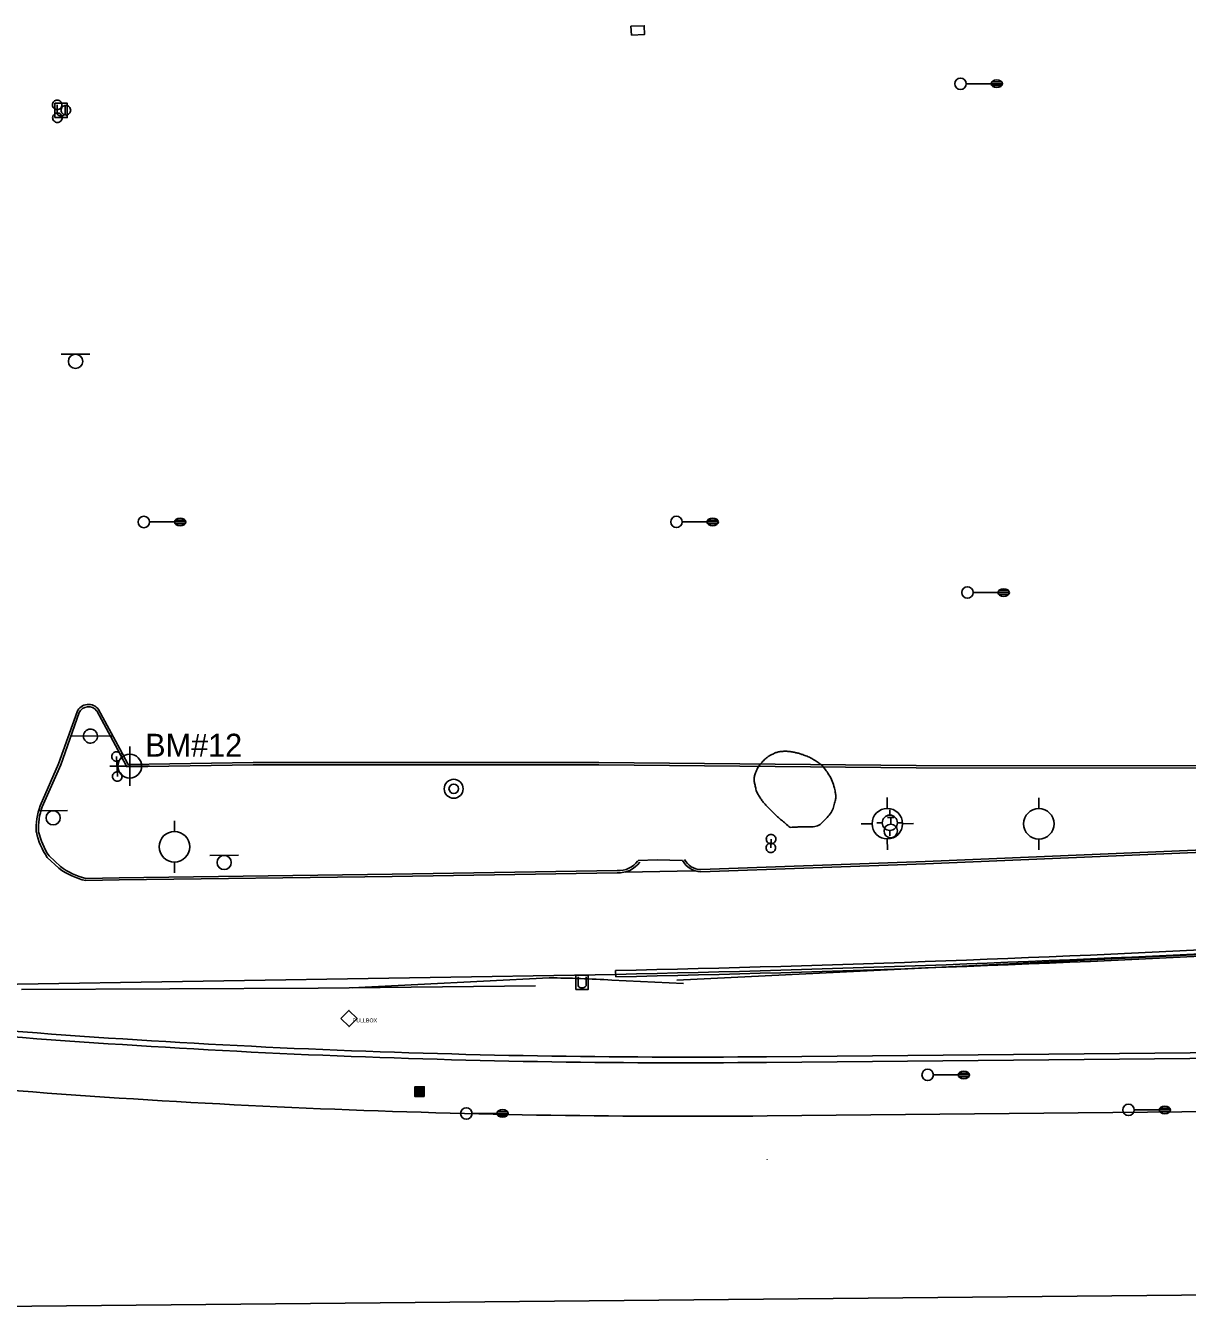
# Model space of a CAD drawing. Extents: x 2145380 to 2157287, y 139568 to 149130.
# Drawn here: x 2146552.5 to 2146856.9, y 143062 to 143399.4 of the extents above; entities that cross this region are included whole.
import ezdxf

# ---------------------------------------------------------------- set-up
doc = ezdxf.new("R2010")
doc.units = 0
for name, color, linetype in [('Default', 7, 'Continuous'), ('PR_PREVIOUSLY CONSTRUCTED', 7, 'Continuous'), ('SURV_Benchmark', 7, 'Continuous'), ('TOPO_Asphalt', 7, 'Continuous'), ('TOPO_Concrete', 7, 'Continuous'), ('TOPO_Curb Back', 7, 'Continuous'), ('TOPO_DRAIN_Inlet Grate', 7, 'Continuous'), ('TOPO_Guardrail', 7, 'Continuous'), ('TOPO_Light Pole', 7, 'Continuous'), ('TOPO_Misc', 7, 'Continuous'), ('TOPO_Power Pole', 7, 'Continuous'), ('TOPO_Power Pullbox', 7, 'Continuous'), ('TOPO_San Manhole', 7, 'Continuous'), ('TOPO_Sign', 7, 'Continuous'), ('TOPO_Tree Line', 7, 'Continuous'), ('TOPO_Water Fire Hydrant', 7, 'Continuous'), ('TOPO_Water Valve', 7, 'Continuous')]:
    doc.layers.add(name, color=color, linetype=linetype)

# ---------------------------------------------------------------- blocks, each defined once
blk = doc.blocks.new('LP')
at = {"layer": 'TOPO_Light Pole'}
blk.add_line((3.81, 0), (20.32, 0), dxfattribs=at)
for points in [[(20.32, 0), (27.94, 0)], [(20.32, 0), (23.5, 0)], [(20.83, 1.27), (27.43, 1.27)], [(20.83, 1.27), (23.5, 1.27)], [(23.71, 1.27), (27.43, 1.27)], [(23.71, 0), (27.94, 0)], [(20.83, -1.27), (27.43, -1.27)], [(20.83, -1.27), (23.5, -1.27)], [(23.71, -1.27), (27.43, -1.27)]]:
    blk.add_lwpolyline(points, dxfattribs=at)
blk.add_circle((0, 0), 3.81, dxfattribs=at)
blk.add_ellipse((24.13, 0), major_axis=(3.81, 0), ratio=0.666667, dxfattribs=at)
blk = doc.blocks.new('POST')
at = {"layer": 'TOPO_Misc'}
for start, end in [(89.99996, 180.00004), (179.99996, 270.00004), (359.99996, 90.00004), (269.99996, 0.00004)]:
    blk.add_arc((-0.01, 0.03), 3.16, start, end, dxfattribs=at)
blk = doc.blocks.new('FIRHYD')
at = {"layer": 'TOPO_Water Fire Hydrant'}
for p, q in [((-0.02, 10.16), (-0.03, 17.34)), ((10.16, 0.02), (17.34, 0.03)), ((-10.16, -0.02), (-17.34, -0.03)), ((0.02, -10.16), (0.03, -17.34))]:
    blk.add_line(p, q, dxfattribs=at)
blk.add_circle((0, 0), 10.16, dxfattribs=at)
blk = doc.blocks.new('CB')
at = {"layer": 'TOPO_Misc'}
for p, q in [((-3.08, 2.99), (3.24, 2.99)), ((-3.08, 2.68), (3.24, 2.68)), ((-3.08, 2.36), (3.24, 2.36)), ((-3.08, 2.05), (3.24, 2.05)), ((-3.08, 1.73), (3.24, 1.73)), ((-3.08, 1.4), (3.24, 1.4)), ((-3.08, 1.1), (3.24, 1.1)), ((-3.08, 0.77), (3.24, 0.77)), ((-3.08, 0.46), (3.24, 0.46)), ((-3.08, 0.14), (3.24, 0.14)), ((-3.08, -0.17), (3.24, -0.17)), ((-3.08, -0.48), (3.24, -0.48)), ((-3.08, -0.8), (3.24, -0.8)), ((-3.08, -1.11), (3.26, -1.11)), ((-3.08, -1.43), (3.26, -1.43)), ((-3.08, -1.75), (3.26, -1.75)), ((-3.08, -2.07), (3.26, -2.07)), ((-3.08, -2.39), (3.26, -2.39)), ((-3.08, -2.7), (3.26, -2.7)), ((-3.08, -3.02), (3.26, -3.02))]:
    blk.add_line(p, q, dxfattribs=at)
blk.add_lwpolyline([(3.26, -3.29), (3.24, 3.05), (-3.09, 3.04), (-3.08, -3.3), (3.26, -3.29)], dxfattribs=at)
blk = doc.blocks.new('POWPOL')
at = {"layer": 'TOPO_Power Pole'}
for p, q in [((0, 10.16), (0, 17.34)), ((0, -10.16), (0, -17.34))]:
    blk.add_line(p, q, dxfattribs=at)
blk.add_circle((0, 0), 10.16, dxfattribs=at)
blk = doc.blocks.new('pulbox')
at = {"layer": 'Default'}
blk.add_lwpolyline([(-5.38, -0.01), (-0.02, 5.42), (5.4, 0.06), (0.05, -5.36), (-5.38, -0.01)], dxfattribs=at)
blk.add_text('PULLBOX', height=2.54, dxfattribs=at).set_placement((2.54, -2.54))
blk = doc.blocks.new('WATVAL')
at = {"layer": 'Default'}
for p, q in [((-2.25, 9), (2.25, 9)), ((0, 4.5), (0, 9))]:
    blk.add_line(p, q, dxfattribs=at)
blk.add_circle((0, 0), 4.5, dxfattribs=at)
blk = doc.blocks.new('EXMHSS')
at = {"layer": 'Default'}
for radius in [6.3, 3.13]:
    blk.add_circle((0, 0), radius, dxfattribs=at)
blk = doc.blocks.new('BM')
at = {"layer": 'SURV_Benchmark'}
for p, q in [((0, 2.49), (0, 4.15)), ((-2.49, 0), (-4.16, 0)), ((4.16, 0), (2.49, 0)), ((0, -4.16), (0, -2.49))]:
    blk.add_line(p, q, dxfattribs=at)
for points in [[(-2.5, 0), (-2.49, 0), (0, 0), (0, -2.49), (0, -2.49)], [(-2.5, 0), (-2.49, 0), (0, 0), (0, -2.49), (0, -2.49)], [(0, 2.49), (0, 2.49), (0, 0), (2.49, 0), (2.49, 0), (2.49, 0)], [(0, 2.49), (0, 2.49), (0, 0), (2.49, 0), (2.49, 0), (2.49, 0), (2.49, 0)]]:
    blk.add_lwpolyline(points, dxfattribs=at)
for start, end in [(90.0638, 180.0068), (0.0638, 90.0068), (0.0638, 90.0068), (180.0638, 270.0068), (180.0638, 270.0068), (269.9472, 359.9927)]:
    blk.add_arc((0, 0), 2.5, start, end, dxfattribs=at)

msp = doc.modelspace()

# ---------------------------------------------------------------- linework, layer by layer
at = {"layer": 'PR_PREVIOUSLY CONSTRUCTED'}
for p, q in [((2146707.09, 143150.12), (2146707.05, 143151.78)), ((2146746.76, 143113.71), (2147732.05, 143123.05)), ((2146353.97, 143061.98), (2147732.51, 143075.05))]:
    msp.add_line(p, q, dxfattribs=at)
for points in [[(2146746.61, 143129.21), (2147125.89, 143132.8), (2147166.18, 143125.18), (2147422.32, 143127.61), (2147722.25, 143136.46), (2147731.92, 143136.55)], [(2146746.63, 143127.71), (2147125.75, 143131.3), (2147166.04, 143123.68), (2147422.35, 143126.11), (2147722.28, 143134.96), (2147731.94, 143135.05)]]:
    msp.add_lwpolyline(points, dxfattribs=at)
for centre, radius, start, end in [((2146580.58, 148904.97), 5754.58, 271.259323, 272.983717), ((2146580.58, 148904.97), 5755.58, 271.259323, 272.983717), ((2146580.58, 148904.97), 5756.24, 271.259323, 272.983717), ((2146725.03, 145405.44), 2277.83, 264.5, 270.54316), ((2146725.03, 145405.44), 2276.33, 264.5, 270.54316), ((2146725.03, 145405.43), 2291.83, 264.5, 270.54316)]:
    msp.add_arc(centre, radius, start, end, dxfattribs=at)
at = {"layer": 'TOPO_Asphalt'}
for p, q in [((2146576.46, 143202.65), (2146576.24, 143207.86)), ((2146727.7, 143177.96), (2146709.51, 143177.61)), ((2146537.09, 143147.98), (2146707.07, 143150.78))]:
    msp.add_line(p, q, dxfattribs=at)
msp.add_lwpolyline([(2146712.97, 143180.61), (2146717.98, 143180.83), (2146724.61, 143180.64)], dxfattribs=at)
at = {"layer": 'TOPO_Concrete'}
msp.add_lwpolyline([(2146746.75, 143102.26), (2146746.75, 143102.21)], dxfattribs=at)
at = {"layer": 'TOPO_Curb Back'}
for points in [[(2146556.23, 143194.94), (2146561.06, 143205.93), (2146565.9, 143219.62)], [(2146556.79, 143194.71), (2146561.62, 143205.7), (2146566.46, 143219.39)], [(2146571.05, 143219.87), (2146576.58, 143209.64), (2146578.98, 143205.21), (2146612.05, 143205.72), (2146702.61, 143205.68), (2146785.83, 143204.89), (2146866.96, 143204.87), (2146925.47, 143204.4), (2146939.15, 143204.34), (2146943.78, 143207.95), (2146941.54, 143212.17)], [(2146571.55, 143220.19), (2146577.11, 143209.93), (2146579.34, 143205.82), (2146612.05, 143206.32), (2146702.61, 143206.28), (2146785.83, 143205.49), (2146866.96, 143205.47), (2146925.48, 143205), (2146938.94, 143204.94), (2146943.01, 143208.11), (2146941.09, 143211.74)], [(2146936.56, 143186.42), (2146861.15, 143182.86), (2146788.22, 143179.79), (2146729.35, 143177.64)], [(2146936.54, 143187.02), (2146861.12, 143183.46), (2146788.2, 143180.39), (2146729.36, 143178.24)], [(2146561.15, 143178.6), (2146558.1, 143181.44)], [(2146561.53, 143179.06), (2146558.56, 143181.83)], [(2146707.46, 143177.43), (2146648.5, 143176.48), (2146576.92, 143175.53), (2146568.17, 143175.36)], [(2146707.48, 143178.03), (2146648.49, 143177.08), (2146576.91, 143176.13), (2146568.24, 143175.96)], [(2146723.1, 143149.31), (2147096.93, 143167.63)]]:
    msp.add_lwpolyline(points, dxfattribs=at)
for centre, radius, start, end in [((2146568.89, 143218.27), 3.28, 35.8736, 155.7101), ((2146568.89, 143218.27), 2.68, 36.6665, 155.1999), ((2146571.29, 143189.22), 16.1, 159.2169, 184.0265), ((2146571.29, 143189.22), 15.5, 159.2728, 183.8644), ((2146573.83, 143192.18), 18.44, 192.5386, 214.1261), ((2146573.83, 143192.18), 19.04, 192.4019, 214.3313), ((2146572.65, 143194.28), 19.45, 233.753, 256.6902), ((2146572.65, 143194.28), 18.85, 233.8598, 256.4606), ((2146707.92, 143184.13), 6.71, 266.1076, 324.0825), ((2146707.92, 143184.13), 6.11, 265.8766, 324.0825), ((2146729.6, 143183.28), 5.65, 207.8693, 267.5079), ((2146729.6, 143183.28), 5.05, 207.8693, 267.2427)]:
    msp.add_arc(centre, radius, start, end, dxfattribs=at)
at = {"layer": 'TOPO_DRAIN_Inlet Grate'}
msp.add_lwpolyline([(2146711.19, 143396.97), (2146714.64, 143397.13), (2146714.54, 143399.4), (2146711.08, 143399.25)], close=True, dxfattribs=at)
at = {"layer": 'TOPO_Guardrail'}
for points in [[(2146551.37, 143146.86), (2146629.12, 143147.21), (2146686.04, 143147.75)], [(2146637.99, 143147.3), (2146689.63, 143149.87)], [(2146706.03, 143149.31), (2146724.88, 143148.43)]]:
    msp.add_lwpolyline(points, dxfattribs=at)
msp.add_arc((2146685.9, 142804.41), 345.49, 86.6594, 89.3802, dxfattribs=at)
at = {"layer": 'TOPO_Misc'}
for p, q in [((2146560.67, 143378.66), (2146560.67, 143376.26)), ((2146562.75, 143376.26), (2146562.75, 143378.67)), ((2146697.21, 143150.16), (2146697.21, 143147.76)), ((2146699.29, 143147.76), (2146699.29, 143150.17))]:
    msp.add_line(p, q, dxfattribs=at)
for points in [[(2146560.08, 143375.35), (2146560.08, 143379.11), (2146563.34, 143379.11), (2146563.34, 143375.35), (2146560.08, 143375.35)], [(2146696.62, 143146.85), (2146696.62, 143150.61), (2146699.88, 143150.61), (2146699.88, 143146.85), (2146696.62, 143146.85)]]:
    msp.add_lwpolyline(points, dxfattribs=at)
for centre in [(2146561.71, 143377.08), (2146698.25, 143148.58)]:
    msp.add_arc(centre, 1.32, 218.3412, 322.0625, dxfattribs=at)
at = {"layer": 'TOPO_Sign'}
for points in [[(2146561.76, 143313.31), (2146569.26, 143313.32)], [(2146565.51, 143313.31), (2146565.51, 143313.31)], [(2146563.65, 143311.45), (2146563.65, 143311.45)], [(2146567.38, 143311.45), (2146567.38, 143311.45)], [(2146565.51, 143309.58), (2146565.51, 143309.58)], [(2146564.27, 143213.21), (2146575.15, 143213.27)], [(2146555.89, 143193.69), (2146563.38, 143193.7)], [(2146557.77, 143191.82), (2146557.77, 143191.82)], [(2146559.64, 143193.69), (2146559.64, 143193.69)], [(2146561.51, 143191.82), (2146561.51, 143191.82)], [(2146559.64, 143189.95), (2146559.64, 143189.95)], [(2146747.71, 143183.96), (2146747.78, 143186.22)], [(2146600.71, 143181.98), (2146608.2, 143181.99)], [(2146604.46, 143181.98), (2146604.46, 143181.98)], [(2146602.59, 143180.11), (2146602.59, 143180.11)], [(2146604.46, 143178.24), (2146604.46, 143178.24)], [(2146606.32, 143180.11), (2146606.32, 143180.11)]]:
    msp.add_lwpolyline(points, dxfattribs=at)
for centre, radius, start, end in [((2146565.51, 143311.45), 1.87, 90, 180), ((2146565.51, 143311.45), 1.87, 360, 90), ((2146565.51, 143311.45), 1.87, 180, 270), ((2146565.51, 143311.45), 1.87, 270, 0), ((2146569.41, 143213.23), 1.84, 47.4196, 227.4196), ((2146569.41, 143213.23), 1.84, 227.4196, 47.4196), ((2146559.64, 143191.82), 1.87, 90, 180), ((2146559.64, 143191.82), 1.87, 180, 270), ((2146559.64, 143191.82), 1.87, 360, 90), ((2146559.64, 143191.82), 1.87, 270, 0), ((2146604.46, 143180.11), 1.87, 90, 180), ((2146604.46, 143180.11), 1.87, 360, 90), ((2146604.46, 143180.11), 1.87, 180, 270), ((2146604.46, 143180.11), 1.87, 270, 0)]:
    msp.add_arc(centre, radius, start, end, dxfattribs=at)
at = {"layer": 'TOPO_Tree Line'}
msp.add_open_spline([(2146752.76, 143189.3), (2146753.6, 143189.35), (2146754.44, 143189.4), (2146755.28, 143189.45), (2146756.33, 143189.51), (2146757.38, 143189.38), (2146758.43, 143189.46), (2146760, 143189.56), (2146761.28, 143190.6), (2146762.46, 143191.91), (2146763.62, 143193.2), (2146764.18, 143194.55), (2146764.54, 143196.07), (2146764.75, 143196.93), (2146764.78, 143197.84), (2146764.59, 143198.68), (2146764.18, 143200.55), (2146763.52, 143202.31), (2146762.38, 143203.98), (2146761.75, 143204.9), (2146761.06, 143205.63), (2146760.18, 143206.26), (2146759.02, 143207.08), (2146757.86, 143207.71), (2146756.56, 143208.21), (2146755.67, 143208.55), (2146754.77, 143208.79), (2146753.85, 143208.98), (2146752.77, 143209.19), (2146751.66, 143209.29), (2146750.58, 143209.21), (2146749.7, 143209.14), (2146748.86, 143208.84), (2146748.02, 143208.42), (2146747.22, 143208.03), (2146746.57, 143207.57), (2146745.93, 143206.93), (2146744.92, 143205.93), (2146744.21, 143204.87), (2146743.73, 143203.57), (2146743.37, 143202.63), (2146743.34, 143201.59), (2146743.53, 143200.65), (2146743.75, 143199.56), (2146744.06, 143198.47), (2146744.68, 143197.47), (2146745.25, 143196.56), (2146745.84, 143195.76), (2146746.57, 143195.01), (2146747.62, 143193.92), (2146748.66, 143192.82), (2146749.8, 143191.84), (2146750.79, 143190.99), (2146751.77, 143190.15), (2146752.76, 143189.3), (2146752.76, 143189.3)], degree=3, dxfattribs=at)

# ---------------------------------------------------------------- block references
at = {"layer": 'SURV_Benchmark', "xscale": 1.25, "yscale": 1.25}
msp.add_blockref('BM', (2146579.7, 143205.36), dxfattribs=at)
at = {"layer": 'TOPO_Light Pole', "xscale": 0.39370000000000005, "yscale": 0.3937000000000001}
for p in [(2146797.44, 143384.2), (2146583.41, 143269.35), (2146722.98, 143269.37), (2146799.25, 143250.86), (2146788.82, 143124.44), (2146667.93, 143114.34), (2146841.48, 143115.27)]:
    msp.add_blockref('LP', p, dxfattribs=at)
at = {"layer": 'TOPO_Misc', "xscale": 0.39370000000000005, "yscale": 0.3937000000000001}
for name, p in [('POST', (2146560.7, 143378.66)), ('POST', (2146562.99, 143377.24)), ('POST', (2146560.75, 143375.29)), ('POST', (2146576.24, 143207.86)), ('POST', (2146576.46, 143202.65)), ('POST', (2146747.71, 143183.96)), ('POST', (2146747.78, 143186.22)), ('CB', (2146655.62, 143120.12))]:
    msp.add_blockref(name, p, dxfattribs=at)
at = {"layer": 'TOPO_Power Pole', "xscale": 0.39370000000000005, "yscale": 0.3937000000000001}
for p in [(2146817.97, 143190.25), (2146591.42, 143184.23)]:
    msp.add_blockref('POWPOL', p, dxfattribs=at)
at = {"layer": 'TOPO_Power Pullbox', "xscale": 0.39370000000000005, "yscale": 0.3937000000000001}
msp.add_blockref('pulbox', (2146637.17, 143139.23), dxfattribs=at)
at = {"layer": 'TOPO_San Manhole', "xscale": 0.39370000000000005, "yscale": 0.3937000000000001}
msp.add_blockref('EXMHSS', (2146664.61, 143199.43), dxfattribs=at)
at = {"layer": 'TOPO_Water Fire Hydrant'}
for p, xscale, yscale in [((2146778.25, 143190.28), 0.39370000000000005, 0.3937000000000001), ((2146778.91, 143190.53), 0.19685000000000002, 0.19685000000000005)]:
    msp.add_blockref('FIRHYD', p, dxfattribs=dict(at, xscale=xscale, yscale=yscale))
at = {"layer": 'TOPO_Water Valve', "xscale": 0.39370000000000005, "yscale": 0.3937000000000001}
msp.add_blockref('WATVAL', (2146779.16, 143188.38), dxfattribs=at)

# ---------------------------------------------------------------- texts
at = {"layer": 'SURV_Benchmark'}
msp.add_text('BM#12', height=6, dxfattribs=at).set_placement((2146583.75, 143207.85))

doc.saveas('drawing.dxf')
